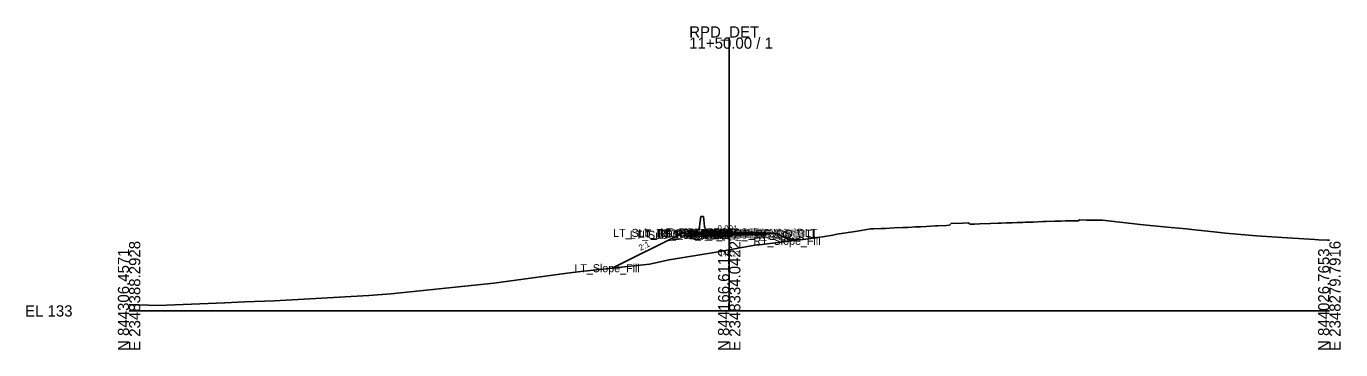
# Model space of a CAD drawing. Extents: x -26 to 2348503, y -10 to 844218.
# Drawn here: x -25.7 to 302.8, y 1490.3 to 1571.1 of the extents above; entities that cross this region are included whole.
import ezdxf

# ---------------------------------------------------------------- set-up
doc = ezdxf.new("R2010")
doc.units = 0
for name, color, linetype in [('Default', 7, 'Continuous'), ('Exist Cross Section Cell', 7, 'Continuous'), ('Exist XS Center Line Elevation Label', 7, 'Continuous'), ('Exist XS Ground Line', 7, 'Continuous'), ('Old_Level_1', 7, 'Continuous'), ('Prop CMT Pvmt Course 1', 7, 'Continuous'), ('Prop CMT Pvmt Course 2', 7, 'Continuous'), ('Prop CMT Pvmt Course 3', 7, 'Continuous'), ('Prop CMT Pvmt Surface', 7, 'Continuous'), ('Prop CMT Pvmt Surface Shoulder', 7, 'Continuous'), ('Prop CMT Shld Paved Course 1', 7, 'Continuous'), ('Prop CMT Shld Paved Course 2', 7, 'Continuous'), ('Prop CMT Shld Paved Course 3', 7, 'Continuous'), ('Prop CMT Slope Grass', 7, 'Continuous'), ('Prop CMT Subgrade Earthwork', 7, 'Continuous'), ('Prop XS Earthwork Shape', 7, 'Continuous'), ('Prop XS SE Text', 7, 'Continuous'), ('Typical Median Barrier CELL', 7, 'Continuous')]:
    doc.layers.add(name, color=color, linetype=linetype)

# ---------------------------------------------------------------- blocks, each defined once
blk = doc.blocks.new('TYPE T DOUBLE FACE BARRIER')
at = {"layer": 'Typical Median Barrier CELL'}
for p, q in [((-0.33, 3.83), (-0.6, 1.3)), ((0, 3.83), (-0.33, 3.83)), ((0, 3.83), (0.33, 3.83)), ((0.33, 3.83), (0.6, 1.3)), ((-0.75, 0.91), (-1.21, 0.25)), ((-1.21, -0.17), (-1.21, 0.25)), ((0, 0), (0, 0)), ((0.75, 0.91), (1.21, 0.25)), ((1.21, -0.17), (1.21, 0.25)), ((-1.21, -0.17), (1.21, -0.17))]:
    blk.add_line(p, q, dxfattribs=at)
for centre, start, end in [((-1.43, 1.38), 325.0039, 353.9447), ((1.43, 1.38), 186.0553, 214.9937)]:
    blk.add_arc(centre, 0.833, start, end, dxfattribs=at)

msp = doc.modelspace()

# ---------------------------------------------------------------- linework, layer by layer
at = {"layer": 'Exist Cross Section Cell'}
for p, q in [((150, 1500), (150, 1568.31)), ((0, 1500), (150, 1500)), ((150, 1500), (300, 1500))]:
    msp.add_line(p, q, dxfattribs=at)
at = {"layer": 'Exist XS Ground Line'}
msp.add_lwpolyline([(0, 1501.62), (7.28, 1501.38), (23.96, 1502), (28.91, 1502.24), (36.3, 1502.53), (42.28, 1502.88), (59.95, 1503.86), (65.4, 1504.23), (91.2, 1506.96), (109.46, 1509.42), (112.93, 1509.81), (130.05, 1511.7), (134.96, 1512.78), (135.48, 1512.87), (142.69, 1514.03), (146.21, 1514.61), (150, 1515.27), (150.42, 1515.35), (156.93, 1516.52), (157.6, 1516.53), (171.75, 1518.25), (175.88, 1518.9), (176.92, 1519.2), (181.46, 1519.85), (185.38, 1520.47), (186.08, 1520.51), (187.97, 1520.59), (188.53, 1520.61), (189.03, 1520.63), (191.2, 1520.72), (193.37, 1520.81), (193.87, 1520.83), (194.67, 1520.88), (196.59, 1520.98), (197.83, 1521.04), (199.26, 1521.11), (201.55, 1521.22), (202.12, 1521.25), (204.27, 1521.37), (205.1, 1521.43), (205.5, 1521.83), (208.35, 1521.93), (209.75, 1521.98), (210.21, 1521.66), (210.59, 1521.69), (211.3, 1521.71), (212.65, 1521.75), (215.34, 1521.85), (217.26, 1521.93), (218, 1521.95), (219.2, 1522), (220.71, 1522.04), (221.97, 1522.07), (222.37, 1522.09), (222.7, 1522.1), (223.38, 1522.11), (224.06, 1522.14), (226.01, 1522.21), (228.39, 1522.3), (228.71, 1522.31), (229.2, 1522.33), (231.41, 1522.39), (232.88, 1522.44), (234.07, 1522.47), (234.59, 1522.49), (235.95, 1522.51), (236.69, 1522.52), (237.2, 1522.53), (237.64, 1522.77), (239.31, 1522.71), (243.3, 1522.66), (252.73, 1521.59), (258.61, 1521.04), (264.2, 1520.47), (266.34, 1520.26), (271.87, 1519.66), (274.07, 1519.42), (274.92, 1519.33), (281.8, 1518.77), (285.65, 1518.47), (289.53, 1518.24), (296.37, 1517.83), (297.25, 1517.78), (299.52, 1517.69), (300, 1517.67)], dxfattribs=at)
at = {"layer": 'Prop CMT Pvmt Course 1'}
for p, q in [((150, 1519.61), (142, 1519.61)), ((142, 1519.61), (142, 1519.36)), ((142, 1519.36), (150, 1519.36)), ((150, 1519.36), (150, 1519.61)), ((150, 1519.61), (158, 1519.6)), ((150, 1519.36), (150, 1519.61)), ((150, 1519.36), (150, 1519.48)), ((150, 1519.48), (150, 1519.48)), ((150, 1519.48), (150, 1519.36)), ((150, 1519.36), (150, 1519.48)), ((150, 1519.48), (150, 1519.48)), ((150, 1519.48), (150, 1519.36)), ((150, 1519.36), (150, 1519.36)), ((158, 1519.35), (150, 1519.36)), ((150, 1519.36), (150, 1519.36)), ((158, 1519.6), (158, 1519.35))]:
    msp.add_line(p, q, dxfattribs=at)
at = {"layer": 'Prop CMT Pvmt Course 2'}
for p, q in [((142, 1519.36), (150, 1519.36)), ((150, 1519.36), (142, 1519.36)), ((142, 1519.36), (142, 1519.36)), ((150, 1519.36), (150, 1519.36)), ((158, 1519.35), (150, 1519.36)), ((150, 1519.36), (150, 1519.36)), ((150, 1519.36), (158, 1519.35)), ((158, 1519.35), (158, 1519.35))]:
    msp.add_line(p, q, dxfattribs=at)
at = {"layer": 'Prop CMT Pvmt Course 3'}
for p, q in [((150, 1519.36), (142, 1519.36)), ((142, 1519.36), (142, 1519.03)), ((142, 1519.03), (150, 1519.02)), ((150, 1519.02), (150, 1519.36)), ((150, 1519.36), (158, 1519.35)), ((150, 1519.02), (150, 1519.36)), ((158, 1519.02), (150, 1519.02)), ((158, 1519.35), (158, 1519.02))]:
    msp.add_line(p, q, dxfattribs=at)
at = {"layer": 'Prop CMT Pvmt Surface'}
for q in [(142, 1519.61), (158, 1519.6)]:
    msp.add_line((150, 1519.61), q, dxfattribs=at)
at = {"layer": 'Prop CMT Pvmt Surface Shoulder'}
for p, q in [((142, 1519.61), (142, 1519.61)), ((158, 1519.6), (158, 1519.6))]:
    msp.add_line(p, q, dxfattribs=at)
at = {"layer": 'Prop CMT Shld Paved Course 1'}
for p, q in [((142, 1519.61), (141.74, 1519.36)), ((141.74, 1519.36), (142, 1519.36)), ((142, 1519.61), (142, 1519.61)), ((142, 1519.36), (142, 1519.61)), ((158, 1519.6), (158, 1519.6)), ((158, 1519.6), (158.26, 1519.35)), ((158, 1519.35), (158, 1519.6)), ((158.26, 1519.35), (158, 1519.35))]:
    msp.add_line(p, q, dxfattribs=at)
at = {"layer": 'Prop CMT Shld Paved Course 2'}
for p, q in [((142, 1519.36), (141.74, 1519.36)), ((141.74, 1519.36), (141.74, 1519.36)), ((141.74, 1519.36), (142, 1519.36)), ((142, 1519.36), (142, 1519.36)), ((158, 1519.35), (158.26, 1519.35)), ((158.26, 1519.35), (158, 1519.35)), ((158, 1519.35), (158, 1519.35)), ((158.26, 1519.35), (158.26, 1519.35))]:
    msp.add_line(p, q, dxfattribs=at)
at = {"layer": 'Prop CMT Shld Paved Course 3'}
for p, q in [((141.24, 1519.35), (140.9, 1519.01)), ((140.9, 1519.01), (142, 1519.03)), ((141.74, 1519.36), (141.24, 1519.35)), ((142, 1519.36), (141.74, 1519.36)), ((142, 1519.03), (142, 1519.36)), ((158, 1519.35), (158.26, 1519.35)), ((158, 1519.02), (158, 1519.35)), ((159.1, 1519), (158, 1519.02)), ((158.26, 1519.35), (158.76, 1519.34)), ((158.76, 1519.34), (159.1, 1519))]:
    msp.add_line(p, q, dxfattribs=at)
at = {"layer": 'Prop CMT Slope Grass'}
for p, q in [((138, 1519.29), (120.77, 1510.67)), ((142, 1519.61), (138, 1519.29)), ((158, 1519.6), (162, 1519.28)), ((162, 1519.28), (165.57, 1517.5))]:
    msp.add_line(p, q, dxfattribs=at)
at = {"layer": 'Prop CMT Subgrade Earthwork'}
for p, q in [((140.9, 1519.01), (140.43, 1519.49)), ((142, 1519.03), (140.9, 1519.01)), ((150, 1519.02), (142, 1519.03)), ((150, 1519.02), (158, 1519.02)), ((158, 1519.02), (159.1, 1519)), ((159.1, 1519), (159.57, 1519.48))]:
    msp.add_line(p, q, dxfattribs=at)
at = {"layer": 'Prop XS Earthwork Shape'}
msp.add_lwpolyline([(140.9, 1519.01), (140.43, 1519.49), (138, 1519.29), (120.77, 1510.67), (130.05, 1511.7), (134.96, 1512.78), (135.48, 1512.87), (142.69, 1514.03), (146.21, 1514.61), (150, 1515.27), (150.42, 1515.35), (156.93, 1516.52), (157.6, 1516.53), (165.57, 1517.5), (162, 1519.28), (159.57, 1519.48), (159.1, 1519), (158, 1519.02), (150, 1519.02), (142, 1519.03)], close=True, dxfattribs=at)

# ---------------------------------------------------------------- block references
at = {"layer": 'Old_Level_1', "yscale": -0.9999999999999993, "rotation": 179.96689577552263}
msp.add_blockref('TYPE T DOUBLE FACE BARRIER', (143.21, 1519.78), dxfattribs=at)

# ---------------------------------------------------------------- texts
at = {"layer": 'Default'}
for s, height, p in [('LT_Sub_Trench_Out_DLT', 2, (120.99, 1518.49)), ('LT_Sub_Trench_Out', 2, (125.11, 1518.01)), ('LT_PS3_Shelf_Out', 2, (127.23, 1518.35)), ('LT_GS_OS_CTL', 2, (127.37, 1518.29)), ('LT_PS3_OEOP', 2, (131.98, 1518.36)), ('LT_PS2_OEOP', 2, (131.98, 1518.36)), ('LT_Sub_OEOT', 2, (132.08, 1518.03)), ('LT_PV3_OEOT', 2, (132.17, 1518.36)), ('LT_PV2_OEOT', 2, (132.17, 1518.36)), ('LT_PV1_OEOT', 2, (132.74, 1518.61)), ('LT_PS1_OEOP', 2, (132.8, 1518.61)), ('RT_Sub_OEEOP', 2, (139.17, 1518.02)), ('LT_Sub_OEEOP', 2, (139.21, 1518.02)), ('RT_PV2_OEEOP', 2, (139.26, 1518.36)), ('RT_PV3_OEEOP', 2, (139.26, 1518.36)), ('LT_PV2_OEEOP', 2, (139.31, 1518.36)), ('LT_PV3_OEEOP', 2, (139.31, 1518.36)), ('RT_PV1_OEEOP', 2, (139.83, 1518.48)), ('LT_PV1_OEEOP', 2, (139.87, 1518.48)), ('RT_PV2_IEEOP', 2, (139.91, 1518.36)), ('LT_PV2_IEEOP', 2, (139.95, 1518.36)), ('RT_Sub_Trench_Out_DLT', 2, (140.09, 1518.48)), ('RT_PV1_IEEOP', 2, (140.47, 1518.48)), ('LT_PV1_IEEOP', 2, (140.52, 1518.48)), ('RT_Sub_Trench_Out', 2, (143.25, 1518)), ('PV2_PGL', 2, (143.91, 1518.36)), ('PV1_PGL', 2, (144.47, 1518.61)), ('RT_PS3_Shelf_Out', 2, (144.69, 1518.34)), ('RT_Sub_OEOT', 2, (148.03, 1518.02)), ('RT_PV3_OEOT', 2, (148.13, 1518.35)), ('RT_PV2_OEOT', 2, (148.13, 1518.35)), ('RT_PS3_OEOP', 2, (148.44, 1518.35)), ('RT_PS2_OEOP', 2, (148.44, 1518.35)), ('RT_PV1_OEOT', 2, (148.69, 1518.6)), ('RT_PS1_OEOP', 2, (148.76, 1518.6)), ('RT_GS_OS_CTL', 2, (151.32, 1518.28)), ('RT_Slope_Fill', 2, (156.04, 1516.5)), ('LT_Slope_Fill', 2, (111.29, 1509.67)), ('-', 0.0001, (0, 1500))]:
    msp.add_text(s, height=height, dxfattribs=at).set_placement(p)
at = {"layer": 'Exist Cross Section Cell'}
for s, p in [('RPD_DET', (140, 1568.31)), ('11+50.00 / 1', (140, 1565.51)), ('EL 133', (-26, 1498.6))]:
    msp.add_text(s, height=2.8, dxfattribs=at).set_placement(p)
for s, p in [('N 844306.4571', (0, 1490)), ('E 2348388.2928', (2.8, 1490)), ('N 844166.6112', (150, 1490)), ('E 2348334.0422', (152.8, 1490)), ('N 844026.7653', (300, 1490)), ('E 2348279.7916', (302.8, 1490))]:
    msp.add_text(s, height=2.8, rotation=90, dxfattribs=at).set_placement(p)
at = {"layer": 'Exist XS Center Line Elevation Label'}
msp.add_text('148.27', height=1.2, dxfattribs=at).set_placement((147.55, 1513.67))
at = {"layer": 'Prop XS SE Text'}
for s, rotation, p in [('0.001', 359.9669, (147.06, 1519.87)), ('2:1', 333.4349, (162.99, 1519.28)), ('2:1', 26.5651, (127.83, 1514.97))]:
    msp.add_text(s, height=1.5, rotation=rotation, dxfattribs=at).set_placement(p)

doc.saveas('drawing.dxf')
